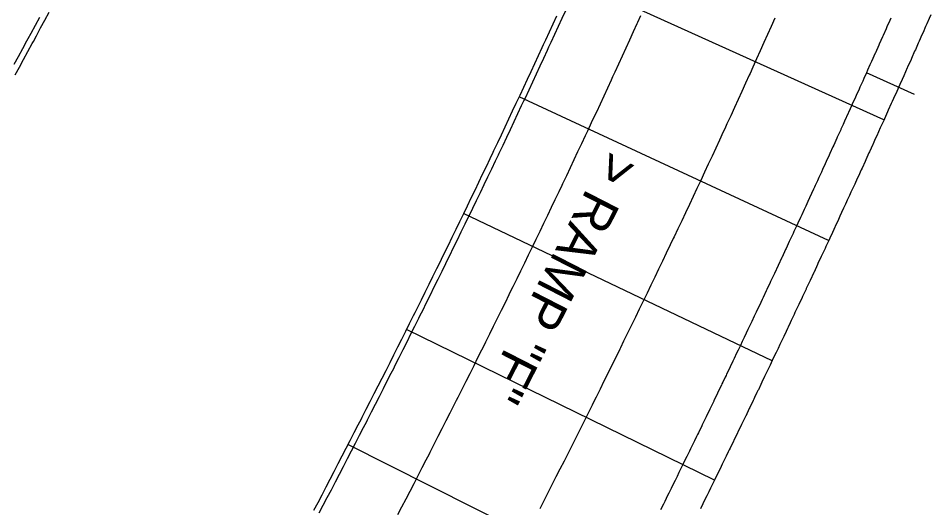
# Model space of a CAD drawing. Extents: x 2145147 to 2158018, y 137519 to 148068.
# Drawn here: x 2150520.6 to 2150624, y 144084.6 to 144140 of the extents above; entities that cross this region are included whole.
import ezdxf

# ---------------------------------------------------------------- set-up
doc = ezdxf.new("R2010")
doc.units = 0
for name, color, linetype in [('PR_Align_Ramp_B', 7, 'Continuous'), ('PR_Align_Ramp_F_Label', 7, 'Continuous'), ('PR_Joint_Contraction', 7, 'Continuous'), ('PR_Joint_Long', 7, 'Continuous'), ('PR_Phasing_Pavement_1', 7, 'Continuous'), ('PR_Road_Concrete', 7, 'Continuous')]:
    doc.layers.add(name, color=color, linetype=linetype)

msp = doc.modelspace()

# ---------------------------------------------------------------- linework, layer by layer
at = {"layer": 'PR_Align_Ramp_B'}
msp.add_lwpolyline([(2150622.21, 144131.35), (2150616.74, 144133.81)], dxfattribs=at)
at = {"layer": 'PR_Joint_Contraction'}
for p, q in [((2150618.72, 144128.48), (2150583.49, 144144.41)), ((2150612.46, 144114.81), (2150577.36, 144131.11)), ((2150606.05, 144101.2), (2150571.06, 144117.9)), ((2150599.5, 144087.66), (2150564.58, 144104.76)), ((2150592.82, 144074.18), (2150557.94, 144091.71))]:
    msp.add_line(p, q, dxfattribs=at)
at = {"layer": 'PR_Joint_Long'}
for points in [[(2150591.12, 144140.26), (2150590.79, 144139.53), (2150590.71, 144139.36), (2150590.3, 144138.45), (2150589.88, 144137.54), (2150589.47, 144136.63), (2150589.05, 144135.72), (2150588.63, 144134.82), (2150588.22, 144133.91), (2150587.96, 144133.36), (2150587.8, 144133), (2150587.38, 144132.1), (2150586.96, 144131.19), (2150586.54, 144130.29), (2150586.12, 144129.38), (2150585.69, 144128.48), (2150585.27, 144127.57), (2150585.1, 144127.21), (2150584.85, 144126.67), (2150584.42, 144125.77), (2150583.99, 144124.86), (2150583.57, 144123.96), (2150583.14, 144123.06), (2150582.71, 144122.16), (2150582.28, 144121.25), (2150582.2, 144121.07), (2150581.85, 144120.35), (2150581.42, 144119.45), (2150580.99, 144118.55), (2150580.56, 144117.65), (2150580.13, 144116.75), (2150579.7, 144115.85), (2150579.26, 144114.96), (2150579.26, 144114.95), (2150578.83, 144114.06), (2150578.39, 144113.16), (2150577.95, 144112.26), (2150577.52, 144111.36), (2150577.08, 144110.47), (2150576.64, 144109.57), (2150576.28, 144108.85), (2150576.2, 144108.67), (2150575.76, 144107.78), (2150575.32, 144106.88), (2150574.87, 144105.99), (2150574.43, 144105.09), (2150573.99, 144104.2), (2150573.54, 144103.31), (2150573.27, 144102.76), (2150573.1, 144102.41), (2150572.65, 144101.52), (2150572.21, 144100.63), (2150571.76, 144099.73), (2150571.31, 144098.84), (2150570.86, 144097.95), (2150570.41, 144097.06), (2150570.22, 144096.69), (2150569.96, 144096.17), (2150569.51, 144095.28), (2150569.06, 144094.39), (2150568.6, 144093.5), (2150568.15, 144092.61), (2150567.69, 144091.72), (2150567.24, 144090.83), (2150567.14, 144090.64), (2150566.78, 144089.94), (2150566.33, 144089.06), (2150565.87, 144088.17), (2150565.41, 144087.28), (2150564.95, 144086.4), (2150564.49, 144085.51), (2150564.03, 144084.63), (2150564.02, 144084.61), (2150563.57, 144083.74)], [(2150606.36, 144140), (2150605.95, 144139.08), (2150605.54, 144138.16), (2150605.12, 144137.24), (2150604.71, 144136.32), (2150604.29, 144135.4), (2150603.87, 144134.48), (2150603.54, 144133.74), (2150603.45, 144133.56), (2150603.03, 144132.64), (2150602.62, 144131.72), (2150602.19, 144130.8), (2150601.77, 144129.88), (2150601.35, 144128.96), (2150600.93, 144128.05), (2150600.67, 144127.49), (2150600.5, 144127.13), (2150600.08, 144126.21), (2150599.66, 144125.29), (2150599.23, 144124.38), (2150598.8, 144123.46), (2150598.37, 144122.55), (2150597.95, 144121.63), (2150597.77, 144121.26), (2150597.52, 144120.72), (2150597.09, 144119.8), (2150596.66, 144118.89), (2150596.22, 144117.97), (2150595.79, 144117.06), (2150595.36, 144116.15), (2150594.93, 144115.24), (2150594.83, 144115.05), (2150594.49, 144114.32), (2150594.05, 144113.41), (2150593.62, 144112.5), (2150593.18, 144111.59), (2150592.74, 144110.68), (2150592.3, 144109.77), (2150591.86, 144108.86), (2150591.86, 144108.85), (2150591.42, 144107.95), (2150590.98, 144107.04), (2150590.54, 144106.13), (2150590.1, 144105.22), (2150589.65, 144104.32), (2150589.21, 144103.41), (2150588.85, 144102.68), (2150588.76, 144102.5), (2150588.32, 144101.59), (2150587.87, 144100.69), (2150587.42, 144099.78), (2150586.98, 144098.88), (2150586.53, 144097.97), (2150586.08, 144097.07), (2150585.8, 144096.51), (2150585.63, 144096.16), (2150585.17, 144095.26), (2150584.72, 144094.35), (2150584.27, 144093.45), (2150583.82, 144092.55), (2150583.36, 144091.65), (2150582.91, 144090.75), (2150582.72, 144090.37), (2150582.45, 144089.84), (2150581.99, 144088.94), (2150581.53, 144088.04), (2150581.08, 144087.14), (2150580.62, 144086.24), (2150580.16, 144085.34), (2150579.7, 144084.44)], [(2150619.51, 144140.02), (2150619.39, 144139.75), (2150619.07, 144139.04), (2150618.97, 144138.82), (2150618.63, 144138.05), (2150618.56, 144137.89), (2150618.2, 144137.07), (2150618.15, 144136.96), (2150617.76, 144136.09), (2150617.73, 144136.03), (2150617.32, 144135.1)], [(2150617.32, 144135.1), (2150617.14, 144134.72), (2150616.88, 144134.14), (2150616.74, 144133.81), (2150616.45, 144133.17), (2150616.33, 144132.89), (2150616.01, 144132.2), (2150615.92, 144131.98), (2150615.58, 144131.24), (2150615.5, 144131.07), (2150615.14, 144130.27), (2150615.09, 144130.16), (2150614.71, 144129.31), (2150614.68, 144129.25), (2150614.27, 144128.34), (2150614.27, 144128.34), (2150614.11, 144127.98), (2150613.85, 144127.43), (2150613.83, 144127.38), (2150613.44, 144126.52), (2150613.39, 144126.41), (2150613.03, 144125.61), (2150612.95, 144125.45), (2150612.61, 144124.7), (2150612.51, 144124.49), (2150612.19, 144123.79), (2150612.07, 144123.52), (2150611.78, 144122.88), (2150611.63, 144122.56), (2150611.36, 144121.97), (2150611.19, 144121.6), (2150610.94, 144121.06), (2150610.86, 144120.88), (2150610.75, 144120.63), (2150610.52, 144120.15), (2150610.3, 144119.67), (2150610.1, 144119.25), (2150609.86, 144118.71), (2150609.68, 144118.34), (2150609.41, 144117.75), (2150609.26, 144117.43), (2150608.97, 144116.79), (2150608.84, 144116.52), (2150608.52, 144115.83), (2150608.42, 144115.62), (2150608.07, 144114.87), (2150608, 144114.71), (2150607.63, 144113.91), (2150607.58, 144113.8), (2150607.57, 144113.79), (2150607.18, 144112.95), (2150607.15, 144112.9), (2150606.73, 144111.99), (2150606.73, 144111.99), (2150606.3, 144111.09), (2150606.28, 144111.03), (2150605.88, 144110.18), (2150605.83, 144110.07), (2150605.45, 144109.28), (2150605.38, 144109.11), (2150605.03, 144108.37), (2150604.92, 144108.15), (2150604.6, 144107.47), (2150604.47, 144107.2), (2150604.24, 144106.72), (2150604.17, 144106.56), (2150604.02, 144106.24), (2150603.74, 144105.66), (2150603.56, 144105.28), (2150603.31, 144104.76), (2150603.11, 144104.33), (2150602.88, 144103.85), (2150602.65, 144103.37), (2150602.45, 144102.95), (2150602.2, 144102.41), (2150602.02, 144102.05), (2150601.74, 144101.46), (2150601.59, 144101.15), (2150601.28, 144100.5), (2150601.16, 144100.25), (2150600.88, 144099.67), (2150600.82, 144099.55), (2150600.73, 144099.34), (2150600.46, 144098.79), (2150600.36, 144098.59), (2150600.29, 144098.44), (2150599.91, 144097.64), (2150599.86, 144097.54), (2150599.44, 144096.68), (2150599.42, 144096.64), (2150598.99, 144095.74), (2150598.98, 144095.73), (2150598.55, 144094.84), (2150598.52, 144094.78), (2150598.12, 144093.94), (2150598.06, 144093.82), (2150597.68, 144093.04), (2150597.6, 144092.87), (2150597.48, 144092.63), (2150597.24, 144092.14), (2150597.13, 144091.92), (2150596.8, 144091.24), (2150596.67, 144090.97), (2150596.36, 144090.35), (2150596.2, 144090.02), (2150595.92, 144089.45), (2150595.74, 144089.06), (2150595.48, 144088.55), (2150595.27, 144088.11), (2150595.04, 144087.65), (2150594.8, 144087.16), (2150594.6, 144086.75), (2150594.33, 144086.21), (2150594.16, 144085.86), (2150594.04, 144085.62), (2150593.87, 144085.26), (2150593.72, 144084.96), (2150593.4, 144084.31)]]:
    msp.add_lwpolyline(points, dxfattribs=at)
at = {"layer": 'PR_Phasing_Pavement_1'}
for points in [[(2150520.09, 144134.79), (2150520.58, 144135.67), (2150521.06, 144136.56), (2150521.54, 144137.45), (2150521.68, 144137.7), (2150522.02, 144138.33), (2150522.51, 144139.22), (2150522.99, 144140.11)], [(2150520.19, 144133.58), (2150520.68, 144134.47), (2150521.16, 144135.35), (2150521.65, 144136.24), (2150522.13, 144137.13), (2150522.27, 144137.38), (2150522.61, 144138.01), (2150523.09, 144138.9), (2150523.57, 144139.79), (2150524.06, 144140.68)]]:
    msp.add_lwpolyline(points, dxfattribs=at)
at = {"layer": 'PR_Road_Concrete'}
for points in [[(2150582.61, 144140.86), (2150582.19, 144139.96), (2150581.78, 144139.06), (2150581.37, 144138.16), (2150580.95, 144137.26), (2150580.7, 144136.72), (2150580.54, 144136.36), (2150580.12, 144135.46), (2150579.7, 144134.56), (2150579.28, 144133.66), (2150578.87, 144132.76), (2150578.45, 144131.87), (2150578.03, 144130.97), (2150577.86, 144130.61), (2150577.6, 144130.07), (2150577.18, 144129.17), (2150576.76, 144128.28), (2150576.34, 144127.38), (2150575.91, 144126.49), (2150575.49, 144125.59), (2150575.06, 144124.69), (2150574.97, 144124.51), (2150574.64, 144123.8), (2150574.21, 144122.91), (2150573.78, 144122.01), (2150573.35, 144121.12), (2150572.92, 144120.22), (2150572.49, 144119.33), (2150572.06, 144118.44), (2150572.06, 144118.43), (2150571.63, 144117.55), (2150571.19, 144116.66), (2150570.76, 144115.76), (2150570.33, 144114.87), (2150569.89, 144113.98), (2150569.46, 144113.09), (2150569.1, 144112.37), (2150569.02, 144112.2), (2150568.58, 144111.31), (2150568.14, 144110.42), (2150567.7, 144109.53), (2150567.26, 144108.65), (2150566.82, 144107.76), (2150566.38, 144106.87), (2150566.11, 144106.33), (2150565.94, 144105.98), (2150565.5, 144105.1), (2150565.05, 144104.21), (2150564.61, 144103.32), (2150564.16, 144102.44), (2150563.72, 144101.55), (2150563.27, 144100.67), (2150563.09, 144100.3), (2150562.82, 144099.78), (2150562.37, 144098.9), (2150561.93, 144098.02), (2150561.48, 144097.13), (2150561.03, 144096.25), (2150560.57, 144095.37), (2150560.12, 144094.48), (2150560.03, 144094.3), (2150559.67, 144093.6), (2150559.22, 144092.72), (2150558.76, 144091.84), (2150558.31, 144090.96), (2150557.85, 144090.08), (2150557.39, 144089.2), (2150556.94, 144088.32), (2150556.93, 144088.31), (2150556.48, 144087.44), (2150556.02, 144086.56), (2150555.56, 144085.69), (2150555.1, 144084.81), (2150554.64, 144083.93)], [(2150581.59, 144140.24), (2150581.17, 144139.34), (2150580.76, 144138.44), (2150580.35, 144137.54), (2150580.1, 144137), (2150579.93, 144136.64), (2150579.51, 144135.74), (2150579.1, 144134.84), (2150578.68, 144133.94), (2150578.26, 144133.05), (2150577.84, 144132.15), (2150577.42, 144131.25), (2150577.25, 144130.89), (2150577, 144130.35), (2150576.58, 144129.46), (2150576.16, 144128.56), (2150575.73, 144127.67), (2150575.31, 144126.77), (2150574.89, 144125.88), (2150574.46, 144124.98), (2150574.37, 144124.8), (2150574.03, 144124.09), (2150573.61, 144123.19), (2150573.18, 144122.3), (2150572.75, 144121.41), (2150572.32, 144120.51), (2150571.89, 144119.62), (2150571.46, 144118.73), (2150571.46, 144118.72), (2150571.03, 144117.84), (2150570.59, 144116.95), (2150570.16, 144116.06), (2150569.73, 144115.17), (2150569.29, 144114.27), (2150568.86, 144113.39), (2150568.5, 144112.67), (2150568.42, 144112.5), (2150567.98, 144111.61), (2150567.54, 144110.72), (2150567.11, 144109.83), (2150566.67, 144108.94), (2150566.23, 144108.05), (2150565.79, 144107.17), (2150565.52, 144106.63), (2150565.34, 144106.28), (2150564.9, 144105.39), (2150564.46, 144104.51), (2150564.01, 144103.62), (2150563.57, 144102.74), (2150563.12, 144101.85), (2150562.68, 144100.97), (2150562.49, 144100.6), (2150562.23, 144100.08), (2150561.78, 144099.2), (2150561.33, 144098.32), (2150560.88, 144097.44), (2150560.43, 144096.55), (2150559.98, 144095.67), (2150559.53, 144094.79), (2150559.43, 144094.6), (2150559.08, 144093.91), (2150558.62, 144093.03), (2150558.17, 144092.15), (2150557.71, 144091.27), (2150557.26, 144090.39), (2150556.8, 144089.51), (2150556.34, 144088.63), (2150556.34, 144088.62), (2150555.89, 144087.75), (2150555.43, 144086.87), (2150554.97, 144085.99), (2150554.51, 144085.12), (2150554.05, 144084.24)], [(2150624.04, 144140.38), (2150623.87, 144139.99), (2150623.6, 144139.39), (2150623.45, 144139.06), (2150623.16, 144138.4), (2150623.04, 144138.12), (2150622.73, 144137.41), (2150622.63, 144137.19), (2150622.29, 144136.43), (2150622.21, 144136.26), (2150621.85, 144135.44), (2150621.8, 144135.33), (2150621.41, 144134.45), (2150621.38, 144134.4), (2150620.97, 144133.47)], [(2150620.97, 144133.47), (2150620.79, 144133.08), (2150620.53, 144132.5), (2150620.38, 144132.17), (2150620.1, 144131.53), (2150619.97, 144131.25), (2150619.66, 144130.56), (2150619.56, 144130.34), (2150619.22, 144129.59), (2150619.15, 144129.42), (2150618.79, 144128.62), (2150618.74, 144128.51), (2150618.35, 144127.66), (2150618.32, 144127.6), (2150617.91, 144126.69), (2150617.91, 144126.68), (2150617.75, 144126.33), (2150617.49, 144125.77), (2150617.47, 144125.72), (2150617.08, 144124.86), (2150617.03, 144124.75), (2150616.66, 144123.95), (2150616.59, 144123.79), (2150616.25, 144123.03), (2150616.15, 144122.82), (2150615.83, 144122.12), (2150615.71, 144121.86), (2150615.41, 144121.21), (2150615.27, 144120.89), (2150614.99, 144120.3), (2150614.82, 144119.92), (2150614.57, 144119.39), (2150614.49, 144119.2), (2150614.38, 144118.96), (2150614.15, 144118.48), (2150613.93, 144118), (2150613.73, 144117.57), (2150613.49, 144117.03), (2150613.31, 144116.66), (2150613.04, 144116.07), (2150612.89, 144115.75), (2150612.59, 144115.1), (2150612.47, 144114.84), (2150612.15, 144114.14), (2150612.05, 144113.93), (2150611.7, 144113.18), (2150611.62, 144113.02), (2150611.25, 144112.21), (2150611.2, 144112.11), (2150611.19, 144112.1), (2150610.8, 144111.25), (2150610.78, 144111.2), (2150610.35, 144110.29), (2150610.35, 144110.29), (2150609.92, 144109.39), (2150609.9, 144109.33), (2150609.5, 144108.48), (2150609.45, 144108.37), (2150609.07, 144107.57), (2150608.99, 144107.41), (2150608.64, 144106.66), (2150608.54, 144106.45), (2150608.21, 144105.76), (2150608.09, 144105.49), (2150607.86, 144105.01), (2150607.79, 144104.85), (2150607.63, 144104.53), (2150607.36, 144103.94), (2150607.18, 144103.57), (2150606.93, 144103.04), (2150606.72, 144102.61), (2150606.49, 144102.13), (2150606.26, 144101.65), (2150606.06, 144101.23), (2150605.81, 144100.69), (2150605.63, 144100.32), (2150605.35, 144099.73), (2150605.2, 144099.42), (2150604.89, 144098.77), (2150604.76, 144098.52), (2150604.49, 144097.93), (2150604.43, 144097.82), (2150604.33, 144097.61), (2150604.06, 144097.05), (2150603.97, 144096.86), (2150603.9, 144096.71), (2150603.51, 144095.9), (2150603.46, 144095.8), (2150603.05, 144094.94), (2150603.03, 144094.9), (2150602.59, 144094), (2150602.58, 144093.99), (2150602.15, 144093.1), (2150602.12, 144093.03), (2150601.71, 144092.19), (2150601.66, 144092.08), (2150601.28, 144091.29), (2150601.19, 144091.12), (2150601.08, 144090.88), (2150600.84, 144090.39), (2150600.73, 144090.17), (2150600.4, 144089.49), (2150600.26, 144089.21), (2150599.96, 144088.59), (2150599.79, 144088.26), (2150599.52, 144087.69), (2150599.33, 144087.3), (2150599.07, 144086.79), (2150598.86, 144086.35), (2150598.63, 144085.89), (2150598.39, 144085.4), (2150598.19, 144084.99), (2150597.92, 144084.44)]]:
    msp.add_lwpolyline(points, dxfattribs=at)

# ---------------------------------------------------------------- texts
at = {"layer": 'PR_Align_Ramp_F_Label'}
msp.add_text('> RAMP "F"', height=4.3, rotation=242.8694, dxfattribs=at).set_placement((2150587.31, 144125.25))

doc.saveas('drawing.dxf')
